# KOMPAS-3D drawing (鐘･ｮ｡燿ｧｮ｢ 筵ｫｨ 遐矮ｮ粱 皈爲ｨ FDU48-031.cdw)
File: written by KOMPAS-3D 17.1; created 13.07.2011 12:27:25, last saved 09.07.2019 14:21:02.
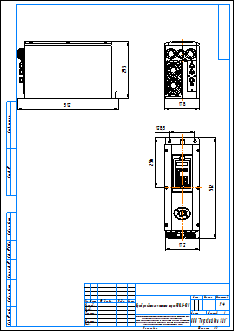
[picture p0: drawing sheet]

Sheet 1: A3, portrait

Title block, sheet 1: name: Преобразователи частоты серии FDU48-031; scale: 1:4; sheets: 1; sheet format: A3; stored path: \\adlc.lan\data\АДЛ_ПКД\3D-модели\Поставщики\Оборудование Emotron\Преобразователи частоты\Серия FDU 2.0\KOMPAS 2D\Преобразователи частоты серии FDU48-031.cdw

Views: Спереди 1
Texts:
  Рама для чертежей
  Лит-Масса-Масштаб
  Материал-Предприятие
  Масштаб
  Изм.
  Лист
  № докум.
  Подп.
  Дата
  Лит.
  Разраб.
  Пров.
  Т.контр.
  Листов
  Внимание! Данный продукт является объектом авторского права ООО «Торговый Дом АДЛ».
  Запрещается изменение, копирование, распространение
  (в том числе путем копирования на другие сайты и ресурсы в Интернете)
  или любое иное использование информации и объектов без предварительного
  согласия правообладателя (ООО «Торговый Дом АДЛ»).
  Н.контр.
  Утв.
  ООО "Торговый дом АДЛ"
  Изменение
  Номер документа
  Подпись
  Обозначение документа
  Наименование изделия
  Масса изделия по ГОСТ 2.109-73
  Порядковый номер листа
  Общее количество листов в документе
  Характер работы, выполненной лицом, подписавшим документ
  Наименование или индекс предприятия, выпускающего документ
  Инв. № подл.
  Подп. и дата
  Взам. инв. №
  Инв. № дубл.
  Инвентарный номер подлинника по ГОСТ 2.501-68
  Подпись принявшего подлинник в отдел технической документации
  Инвентарный номер подлинника, взамен которого выпущен данный подлинник
  Инвентарный номер дубликата по ГОСТ 2.502-68
  Подпись принявшего дубликат в отдел технической документации
  Справ. №
  Перв. примен.
  Обозначение документа, взамен или на основании которого выпущен данный документ
  Обозначение документа, в котором впервые записан данный документ
  Подпись лица, копировавшего чертеж
  Обозначение формата листа
  !Рама для чертежа
Dimensions and other numbers on the sheet: 178; 512; 128,5; 172; 293; 256; 1:4; 1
